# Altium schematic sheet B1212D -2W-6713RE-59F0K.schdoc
size 277 x 190 mm; Device: default297x210; Symbol: default297x210; Name: default297x210; Size: "A4"; Id: /; File: EV_CMP6713-E01; Sheet: /
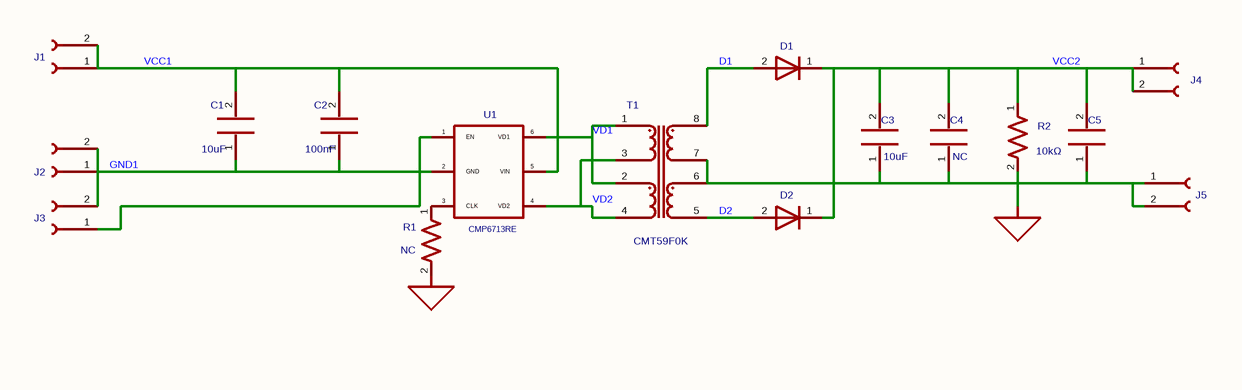
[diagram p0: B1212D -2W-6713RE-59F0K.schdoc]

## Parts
C1  10uF  [coileasy:C_0603]
C2  100nF  [coileasy:C_0603]
C3  10uF  [coileasy:C_0805]
C4  NC  [coileasy:C_0805]
C5  100nF  [coileasy:C_0603]  (value not drawn)
D1  B5819WS  [coileasy:SOD-123FL]  (value not drawn)
D2  B5819WS  [coileasy:SOD-123FL]  (value not drawn)
J1  HX PZ2.54-1x2P ZZ  [coileasy:PinHeader_1x02_P2.54mm_Vertical]  (value not drawn)
J2  HX PZ2.54-1x2P ZZ  [coileasy:PinHeader_1x02_P2.54mm_Vertical]  (value not drawn)
J3  HX PZ2.54-1x2P ZZ  [coileasy:PinHeader_1x02_P2.54mm_Vertical]  (value not drawn)
J4  HX PZ2.54-1x2P ZZ  [coileasy:PinHeader_1x02_P2.54mm_Vertical]  (value not drawn)
J5  HX PZ2.54-1x2P ZZ  [coileasy:PinHeader_1x02_P2.54mm_Vertical]  (value not drawn)
R1  value NC  [coileasy:R_0603]  (hidden comment: R)
R2  10kΩ  [coileasy:R_0603]
T1  CMT59F0K  [My Library:CMT59F0K]
U1  CMP6713RE  [My Library:SOT-23-6]

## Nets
GND1: C1.1 C2.1 J2.1(Pin_1) J2.2(Pin_2) J3.2(Pin_2) R1.2 U1.2(GND)
GND2: C3.1 C4.1 C5.1 J5.1(Pin_1) J5.2(Pin_2) R2.2 T1.6 T1.7
D1: D1.2(A) T1.8
D2: D2.2(A) T1.5
VCC1: C1.2 C2.2 J1.1(Pin_1) J1.2(Pin_2) U1.5(VIN)
VCC2: C3.2 C4.2 C5.2 D1.1(K) D2.1(K) J4.1(Pin_1) J4.2(Pin_2) R2.1
VD1: T1.1 T1.2 U1.6(VD1)
VD2: T1.3 T1.4 U1.4(VD2)
NetJ3_1: J3.1(Pin_1) U1.1(EN)
NetR1_1: R1.1 U1.3(CLK)

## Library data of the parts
C1 C3 = CL10A106MA8NRNC: 容值:10uF;精度:±20%;额定电压:25V;温度系数:X5R;; Manufacturer: SAMSUNG(三星); Symbol: My_Library_C; Add into BOM: yes; 3D Model: ac125912035d415993ca9572d50418b1; 3D Model Transform: 62.992,31.496,0,0,0,0,0,0,0; Tolerance: ±20%; Voltage Rating: 25V; Temperature Coefficient: X5R; ki_keywords: cap capacitor; ki_fp_filters: C_*; ModelName: C0603_L1.6-W0.8-H0.8
C2 = CC0603KRX7R9BB104: 容值:100nF;精度:±10%;额定电压:50V;温度系数:X7R;; Manufacturer: YAGEO(国巨); Symbol: My_Library_C; Add into BOM: yes; 3D Model: ac125912035d415993ca9572d50418b1; 3D Model Transform: 62.992,31.496,0,0,0,0,0,0,0; Tolerance: ±10%; Voltage Rating: 50V; Temperature Coefficient: X7R; ki_keywords: cap capacitor; ki_fp_filters: C_*; ModelName: C0603_L1.6-W0.8-H0.8
C4 = My_Library_C: Add into BOM: no; ki_keywords: cap capacitor; ki_fp_filters: C_*; Attribute1: C4
C5 = CC0603KRX7R9BB104: 容值:100nF;精度:±10%;额定电压:50V;温度系数:X7R;; Manufacturer: YAGEO(国巨); Symbol: My_Library_C; Add into BOM: yes; 3D Model: ac125912035d415993ca9572d50418b1; 3D Model Transform: 62.992,31.496,0,0,0,0,0,0,0; Tolerance: ±10%; Voltage Rating: 50V; Temperature Coefficient: X7R; ki_keywords: cap capacitor; ki_fp_filters: C_*; UniqueId: 05d417a4d81547fc; ModelName: C0603_L1.6-W0.8-H0.8
D1 = B5819WS_C64886: 二极管配置:独立式;正向压降(Vf):900mV@3A;直流反向耐压(Vr):40V;整流电流:1A;; Manufacturer: MDD(辰达半导体); Symbol: My_Library_D; Add into BOM: yes; 3D Model: db63db13d9e342eb939127d413d6200b; 3D Model Transform: 104.3305,51.181,0,0,0,0,0,-0.004,0; Diode Configuration: 独立式; Voltage - DC Reverse(Vr): 40V; Current - Rectified: 1A; Reverse Leakage Current (Ir): 1mA@40V; Operating Junction Temperature Range: -55℃~+125℃; Non-Repetitive Peak Forward Surge Current: 25A; Value: D; ki_keywords: diode; ki_fp_filters: TO-???* *_Diode_* *SingleDiode* D_*; ModelName: SOD-323_L1.8-W1.3-LS2.5-RD
D2 = B5819WS_C64886: 二极管配置:独立式;正向压降(Vf):900mV@3A;直流反向耐压(Vr):40V;整流电流:1A;; Manufacturer: MDD(辰达半导体); Symbol: My_Library_D; Add into BOM: yes; 3D Model: db63db13d9e342eb939127d413d6200b; 3D Model Transform: 104.3305,51.181,0,0,0,0,0,-0.004,0; Diode Configuration: 独立式; Voltage - DC Reverse(Vr): 40V; Current - Rectified: 1A; Reverse Leakage Current (Ir): 1mA@40V; Operating Junction Temperature Range: -55℃~+125℃; Non-Repetitive Peak Forward Surge Current: 25A; Value: D; ki_keywords: diode; ki_fp_filters: TO-???* *_Diode_* *SingleDiode* D_*; UniqueId: fa5cd661465da5bc; ModelName: SOD-323_L1.8-W1.3-LS2.5-RD
J1 = HX PZ2.54-1x2P ZZ: 插针结构:1x2P;间距:2.54mm;行距:-;圆针/方针:方针;安装方式:直插;排数:单排;总PIN位数:2P;额定电流:3A;额定电压:1kV;配合针长度:6mm;塑高:2.5mm;端接针长度:3mm;触头材质:黄铜;触头镀层:金;工作温度:-40℃~+105℃;颜色:黑色;; Manufacturer: hanxia(韩下); Symbol: My library_Conn_01x02; Add into BOM: yes; 3D Model: c7a9f3c3e6e34627af2bf939e464cb35; 3D Model Transform: 200,100,0,0,0,0,0,0,-118.11; Pin Structure: 1x2P; Pitch: 2.54mm; Circluar Pins/Square Pins: 方针; Current Rating: 3A; Voltage Rating (Max): 1kV; Value: Conn_01x02; ki_keywords: connector; ki_fp_filters: Connector*:*_1x??_*; Origin Footprint: library:PinHeader_1x02_P2.54mm_Vertical; UniqueId: 9f49826860c2c79d; ModelName: HDR-TH_2P-P2.54-M-LI-1X2P
J2 = HX PZ2.54-1x2P ZZ: 插针结构:1x2P;间距:2.54mm;行距:-;圆针/方针:方针;安装方式:直插;排数:单排;总PIN位数:2P;额定电流:3A;额定电压:1kV;配合针长度:6mm;塑高:2.5mm;端接针长度:3mm;触头材质:黄铜;触头镀层:金;工作温度:-40℃~+105℃;颜色:黑色;; Manufacturer: hanxia(韩下); Symbol: My library_Conn_01x02; Add into BOM: yes; 3D Model: c7a9f3c3e6e34627af2bf939e464cb35; 3D Model Transform: 200,100,0,0,0,0,0,0,-118.11; Pin Structure: 1x2P; Pitch: 2.54mm; Circluar Pins/Square Pins: 方针; Current Rating: 3A; Voltage Rating (Max): 1kV; Value: Conn_01x02; ki_keywords: connector; ki_fp_filters: Connector*:*_1x??_*; Origin Footprint: library:PinHeader_1x02_P2.54mm_Vertical; UniqueId: 42913bc3a3449998; ModelName: HDR-TH_2P-P2.54-M-LI-1X2P
J3 = HX PZ2.54-1x2P ZZ: 插针结构:1x2P;间距:2.54mm;行距:-;圆针/方针:方针;安装方式:直插;排数:单排;总PIN位数:2P;额定电流:3A;额定电压:1kV;配合针长度:6mm;塑高:2.5mm;端接针长度:3mm;触头材质:黄铜;触头镀层:金;工作温度:-40℃~+105℃;颜色:黑色;; Manufacturer: hanxia(韩下); Symbol: My library_Conn_01x02; Add into BOM: yes; 3D Model: c7a9f3c3e6e34627af2bf939e464cb35; 3D Model Transform: 200,100,0,0,0,0,0,0,-118.11; Pin Structure: 1x2P; Pitch: 2.54mm; Circluar Pins/Square Pins: 方针; Current Rating: 3A; Voltage Rating (Max): 1kV; Value: Conn_01x02; ki_keywords: connector; ki_fp_filters: Connector*:*_1x??_*; Origin Footprint: library:PinHeader_1x02_P2.54mm_Vertical; UniqueId: 6ca7fcf0d18ad80e; ModelName: HDR-TH_2P-P2.54-M-LI-1X2P
J4 J5 = HX PZ2.54-1x2P ZZ: 插针结构:1x2P;间距:2.54mm;行距:-;圆针/方针:方针;安装方式:直插;排数:单排;总PIN位数:2P;额定电流:3A;额定电压:1kV;配合针长度:6mm;塑高:2.5mm;端接针长度:3mm;触头材质:黄铜;触头镀层:金;工作温度:-40℃~+105℃;颜色:黑色;; Manufacturer: hanxia(韩下); Symbol: My library_Conn_01x02; Add into BOM: yes; 3D Model: c7a9f3c3e6e34627af2bf939e464cb35; 3D Model Transform: 200,100,0,0,0,0,0,0,-118.11; Pin Structure: 1x2P; Pitch: 2.54mm; Circluar Pins/Square Pins: 方针; Current Rating: 3A; Voltage Rating (Max): 1kV; Value: Conn_01x02; ki_keywords: connector; ki_fp_filters: Connector*:*_1x??_*; Origin Footprint: library:PinHeader_1x02_P2.54mm_Vertical; ModelName: HDR-TH_2P-P2.54-M-LI-1X2P
R1 = My_Library_R: Add into BOM: no; ki_keywords: R res resistor; ki_fp_filters: R_*; UniqueId: 4e166b190d4de1c3; Attribute1: R1
R2 = RC0603FR-0710KL: 电阻类型:厚膜电阻;阻值:10kΩ;精度:±1%;功率:100mW;最大工作电压:75V;温度系数:±100ppm/℃;; Manufacturer: YAGEO(国巨); Symbol: My_Library_R; Add into BOM: yes; 3D Model: fc143cca1e79419f9cd78b61e9279f08; 3D Model Transform: 31.8897,63.7794,0,90,0,0,0,0,0; Tolerance: ±1%; Power(Watts): 100mW; Overload Voltage (Max): 75V; ki_keywords: R res resistor; ki_fp_filters: R_*; ModelName: R0603
T1 = Coileasy library_VPT87DFB01B: Value: ~; UniqueId: cf2c480e5945250c; Attribute1: T1; AddInBom: yes
U1 = My library_CMP6510: Origin Footprint: coileasy:SOT-23-6; UniqueId: 48a4a086d8c42a18; Attribute1: U1; AddInBom: yes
